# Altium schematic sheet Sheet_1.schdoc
size 312 x 205 mm
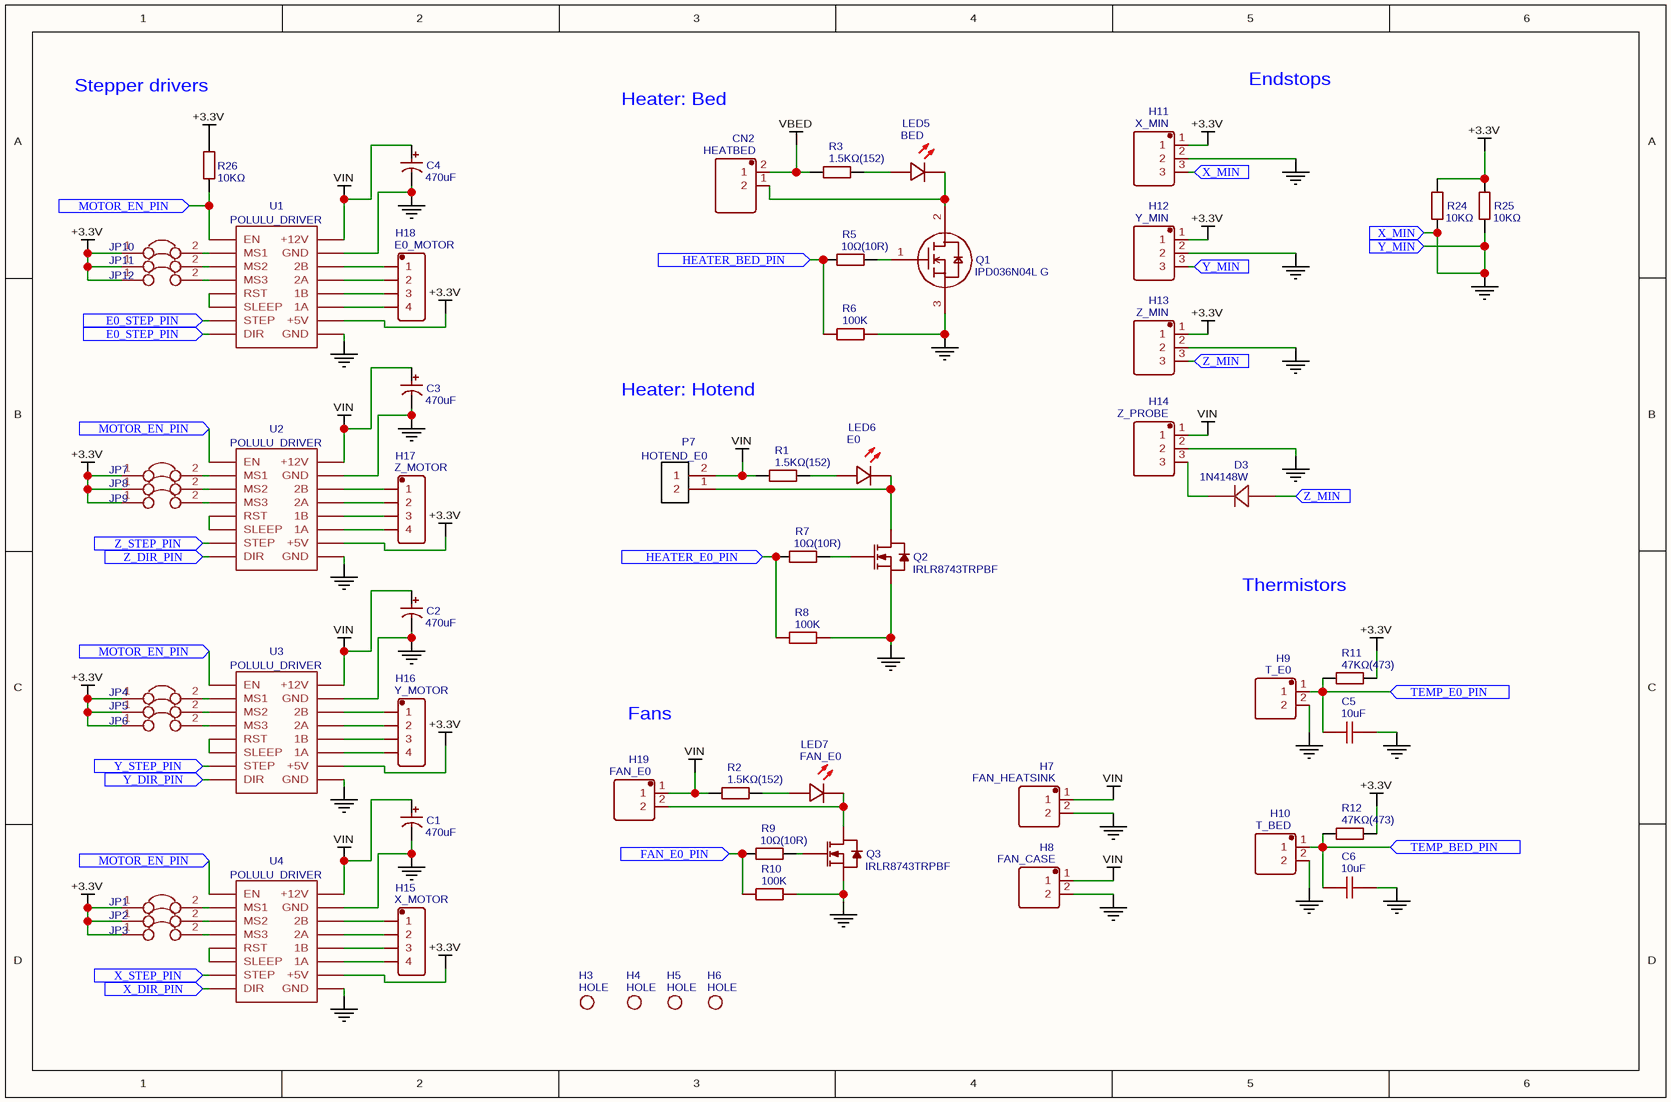
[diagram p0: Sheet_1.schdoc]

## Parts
C1  470uF  [CAP-D10.0XH10.5]
C2  470uF  [CAP-D10.0XH10.5]
C3  470uF  [CAP-D10.0XH10.5]
C4  470uF  [CAP-D10.0XH10.5]
C5  10uF  [0805]
C6  10uF  [0805]
CN2  HEATBED  [MKDS3/2-5.08]
D3  1N4148W  [SOD-123FL]
H3  HOLE  [HOLE_3MM5]
H4  HOLE  [HOLE_3MM5]
H5  HOLE  [HOLE_3MM5]
H6  HOLE  [HOLE_3MM5]
H7  FAN_HEATSINK  [210S-1X2P]
H8  FAN_CASE  [210S-1X2P]
H9  T_E0  [210S-1X2P]
H10  T_BED  [210S-1X2P]
H11  X_MIN  [210S-1X3P]
H12  Y_MIN  [210S-1X3P]
H13  Z_MIN  [210S-1X3P]
H14  Z_PROBE  [210S-1X3P]
H15  X_MOTOR  [DIP-1X4P-2.54MM-M]
H16  Y_MOTOR  [DIP-1X4P-2.54MM-M]
H17  Z_MOTOR  [DIP-1X4P-2.54MM-M]
H18  E0_MOTOR  [DIP-1X4P-2.54MM-M]
H19  FAN_E0  [210S-1X2P]
JP1  JUMPER  [HDR-2X1/2.54]  (value not drawn)
JP2  JUMPER  [HDR-2X1/2.54]  (value not drawn)
JP3  JUMPER  [HDR-2X1/2.54]  (value not drawn)
JP4  JUMPER  [HDR-2X1/2.54]  (value not drawn)
JP5  JUMPER  [HDR-2X1/2.54]  (value not drawn)
JP6  JUMPER  [HDR-2X1/2.54]  (value not drawn)
JP7  JUMPER  [HDR-2X1/2.54]  (value not drawn)
JP8  JUMPER  [HDR-2X1/2.54]  (value not drawn)
JP9  JUMPER  [HDR-2X1/2.54]  (value not drawn)
JP10  JUMPER  [HDR-2X1/2.54]  (value not drawn)
JP11  JUMPER  [HDR-2X1/2.54]  (value not drawn)
JP12  JUMPER  [HDR-2X1/2.54]  (value not drawn)
LED5  BED  [LED-0805]
LED6  E0  [LED-0805]
LED7  FAN_E0  [LED-0805]
P7  HOTEND_E0  [WJ500V-5.08-2P]
Q1  IPD036N04L G  [TO-252-2(2)]
Q2  IRLR8743TRPBF  [TO-252-2]
Q3  IRLR8743TRPBF  [TO-252-2]
R1  1.5KΩ(152)  [0805]
R2  1.5KΩ(152)  [0805]
R3  1.5KΩ(152)  [0805]
R5  10Ω(10R)  [0805]
R6  100K  [0805]
R7  10Ω(10R)  [0805]
R8  100K  [0805]
R9  10Ω(10R)  [0805]
R10  100K  [0805]
R11  47KΩ(473)  [0805]
R12  47KΩ(473)  [0805]
R24  10KΩ  [0805]
R25  10KΩ  [0805]
R26  10KΩ  [0805]
U1  POLULU_DRIVER  [POLULU_DRIVER]
U2  POLULU_DRIVER  [POLULU_DRIVER]
U3  POLULU_DRIVER  [POLULU_DRIVER]
U4  POLULU_DRIVER  [POLULU_DRIVER]

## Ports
E0_STEP_PIN, FAN_E0_PIN, HEATER_BED_PIN, HEATER_E0_PIN, MOTOR_EN_PIN, TEMP_BED_PIN, TEMP_E0_PIN, X_DIR_PIN, X_MIN, X_STEP_PIN, Y_DIR_PIN, Y_MIN, Y_STEP_PIN, Z_DIR_PIN, Z_MIN, Z_STEP_PIN

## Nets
+3.3V: H11.1 H12.1 H13.1 JP1.1 JP2.1 JP3.1 JP4.1 JP5.1 JP6.1 JP7.1 JP8.1 JP9.1 JP10.1 JP11.1 JP12.1 R11.2 R12.2 R24.2 R25.2 R26.2 U1.10(+5V) U2.10(+5V) U3.10(+5V) U4.10(+5V)
GND: C1.2 C2.2 C3.2 C4.2 H7.2 H8.2 H9.2 H10.2 H11.2 H11.3 H12.2 H12.3 H13.2 H14.2 Q1.3(S) Q2.3(S) Q3.3(S) R24.1 R25.1 U1.9(GND) U1.15(GND) U2.9(GND) U2.15(GND) U3.9(GND) U3.15(GND) U4.9(GND) U4.15(GND) ; port X_MIN, port Y_MIN
VBED: CN2.2(1) R3.1
VIN: C1.1 C2.1 C3.1 C4.1 H7.1 H8.1 H14.1 H19.1 P7.2(1) R1.1 R2.1 U1.16(+12V) U2.16(+12V) U3.16(+12V) U4.16(+12V)
E0_STEP_PIN: U1.7(STEP) U1.8(DIR) ; port E0_STEP_PIN
FAN_E0_PIN: R9.1 ; port FAN_E0_PIN
HEATER_BED_PIN: R5.1 ; port HEATER_BED_PIN
HEATER_E0_PIN: R7.1 ; port HEATER_E0_PIN
MOTOR_EN_PIN: R26.1 U1.1(EN) U2.1(EN) U3.1(EN) U4.1(EN) ; port MOTOR_EN_PIN
TEMP_BED_PIN: H10.1 R12.1 ; port TEMP_BED_PIN
TEMP_E0_PIN: H9.1 R11.1 ; port TEMP_E0_PIN
X_DIR_PIN: U4.8(DIR) ; port X_DIR_PIN
X_STEP_PIN: U4.7(STEP) ; port X_STEP_PIN
Y_DIR_PIN: U3.8(DIR) ; port Y_DIR_PIN
Y_STEP_PIN: U3.7(STEP) ; port Y_STEP_PIN
Z_DIR_PIN: U2.8(DIR) ; port Z_DIR_PIN
Z_MIN: D3.2(A) H13.3 ; port Z_MIN
Z_STEP_PIN: U2.7(STEP) ; port Z_STEP_PIN
NetCN2_1: CN2.1(2) LED5.2(-) Q1.2(D)
NetD3_1: D3.1(C) H14.3
NetH15_1: H15.1 U4.14(2B)
NetH15_2: H15.2 U4.13(2A)
NetH15_3: H15.3 U4.12(1B)
NetH15_4: H15.4 U4.11(1A)
NetH16_1: H16.1 U3.14(2B)
NetH16_2: H16.2 U3.13(2A)
NetH16_3: H16.3 U3.12(1B)
NetH16_4: H16.4 U3.11(1A)
NetH17_1: H17.1 U2.14(2B)
NetH17_2: H17.2 U2.13(2A)
NetH17_3: H17.3 U2.12(1B)
NetH17_4: H17.4 U2.11(1A)
NetH18_1: H18.1 U1.14(2B)
NetH18_2: H18.2 U1.13(2A)
NetH18_3: H18.3 U1.12(1B)
NetH18_4: H18.4 U1.11(1A)
NetH19_2: H19.2 LED7.2(-) Q3.4(D)
NetJP1_2: JP1.2 U4.2(MS1)
NetJP2_2: JP2.2 U4.3(MS2)
NetJP3_2: JP3.2 U4.4(MS3)
NetJP4_2: JP4.2 U3.2(MS1)
NetJP5_2: JP5.2 U3.3(MS2)
NetJP6_2: JP6.2 U3.4(MS3)
NetJP7_2: JP7.2 U2.2(MS1)
NetJP8_2: JP8.2 U2.3(MS2)
NetJP9_2: JP9.2 U2.4(MS3)
NetJP10_2: JP10.2 U1.2(MS1)
NetJP11_2: JP11.2 U1.3(MS2)
NetJP12_2: JP12.2 U1.4(MS3)
NetLED5_1: LED5.1(+) R3.2
NetLED6_1: LED6.1(+) R1.2
NetLED6_2: LED6.2(-) P7.1(2) Q2.4(D)
NetLED7_1: LED7.1(+) R2.2
NetQ1_1: Q1.1(G) R5.2
NetQ2_1: Q2.1(G) R7.2
NetQ3_1: Q3.1(G) R9.2
NetU1_5: U1.5(RST) U1.6(SLEEP)
NetU2_5: U2.5(RST) U2.6(SLEEP)
NetU3_5: U3.5(RST) U3.6(SLEEP)
NetU4_5: U4.5(RST) U4.6(SLEEP)

Not connected (* = marked no-connect by the designer): C5 1 2; C6 1 2; R6 1 2; R8 1 2; R10 1 2

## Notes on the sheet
- Stepper drivers
- Heater: Bed
- Endstops
- Heater: Hotend
- Thermistors
- Fans

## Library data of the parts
C1-C4 = (no symbol name): BOM_Manufacturer: SEMTECH; BOM_Manufacturer Part: CK1V471M-CRG10; nameAlias: Capacitance; Contributor: LCSC
C5 C6 = (no symbol name): BOM_Manufacturer: FH; BOM_Manufacturer Part: 0805B106K250NT; nameAlias: Capacitance
CN2 = (no symbol name): BOM_Manufacturer: Phoenix Contact
D3 = (no symbol name): BOM_Manufacturer: Tak Cheong; Contributor: LCSC
H3-H6 = (no symbol name): Contributor: SparkFun
H7-H10 H19 = (no symbol name): BOM_Manufacturer: Ckmtw; BOM_Manufacturer Part: 210S-1*2P L=11.6MMGold-plated black; Contributor: LCSC
H11-H14 = (no symbol name): BOM_Manufacturer: Ckmtw; BOM_Manufacturer Part: 210S-1*3P L=11.6MMGold-plated black; Contributor: LCSC
H15-H18 = (no symbol name): BOM_Manufacturer: Ckmtw; BOM_Manufacturer Part: 210S-1*4P L=11.6MMGold-plated black; Contributor: LCSC
JP1-JP12 = (no symbol name): Contributor: KiCad
LED5-LED7 = (no symbol name): BOM_Manufacturer: Everlight Elec; BOM_Manufacturer Part: 17-21SURC/S530-A2/TR8
P7 = (no symbol name): BOM_Manufacturer: ReliaPro; BOM_Manufacturer Part: WJ500V-5.08-2P-14-00A
Q1 = (no symbol name): BOM_Manufacturer: Infineon; Contributor: LCSC
Q2 Q3 = (no symbol name): BOM_Manufacturer: IR
R1-R3 = (no symbol name): BOM_Manufacturer: YAGEO; BOM_Manufacturer Part: RC0805JR-071K5L; nameAlias: Value
R5 R7 R9 = (no symbol name): BOM_Manufacturer: YAGEO; BOM_Manufacturer Part: RC0805JR-0710RL; nameAlias: Value
R6 R8 R10 = (no symbol name): BOM_Manufacturer: YAGEO; BOM_Manufacturer Part: RC0805DR-07100KL; nameAlias: Resistance (Ohms); Contributor: LCSC
R11 R12 = (no symbol name): BOM_Manufacturer: YAGEO; BOM_Manufacturer Part: RC0805JR-0747KL; nameAlias: Value
R24-R26 = (no symbol name): BOM_Manufacturer: YAGEO; BOM_Manufacturer Part: RC0805JR-0710KL; nameAlias: Value
U1-U4 = (no symbol name): sourceId: KGSeAWhDB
